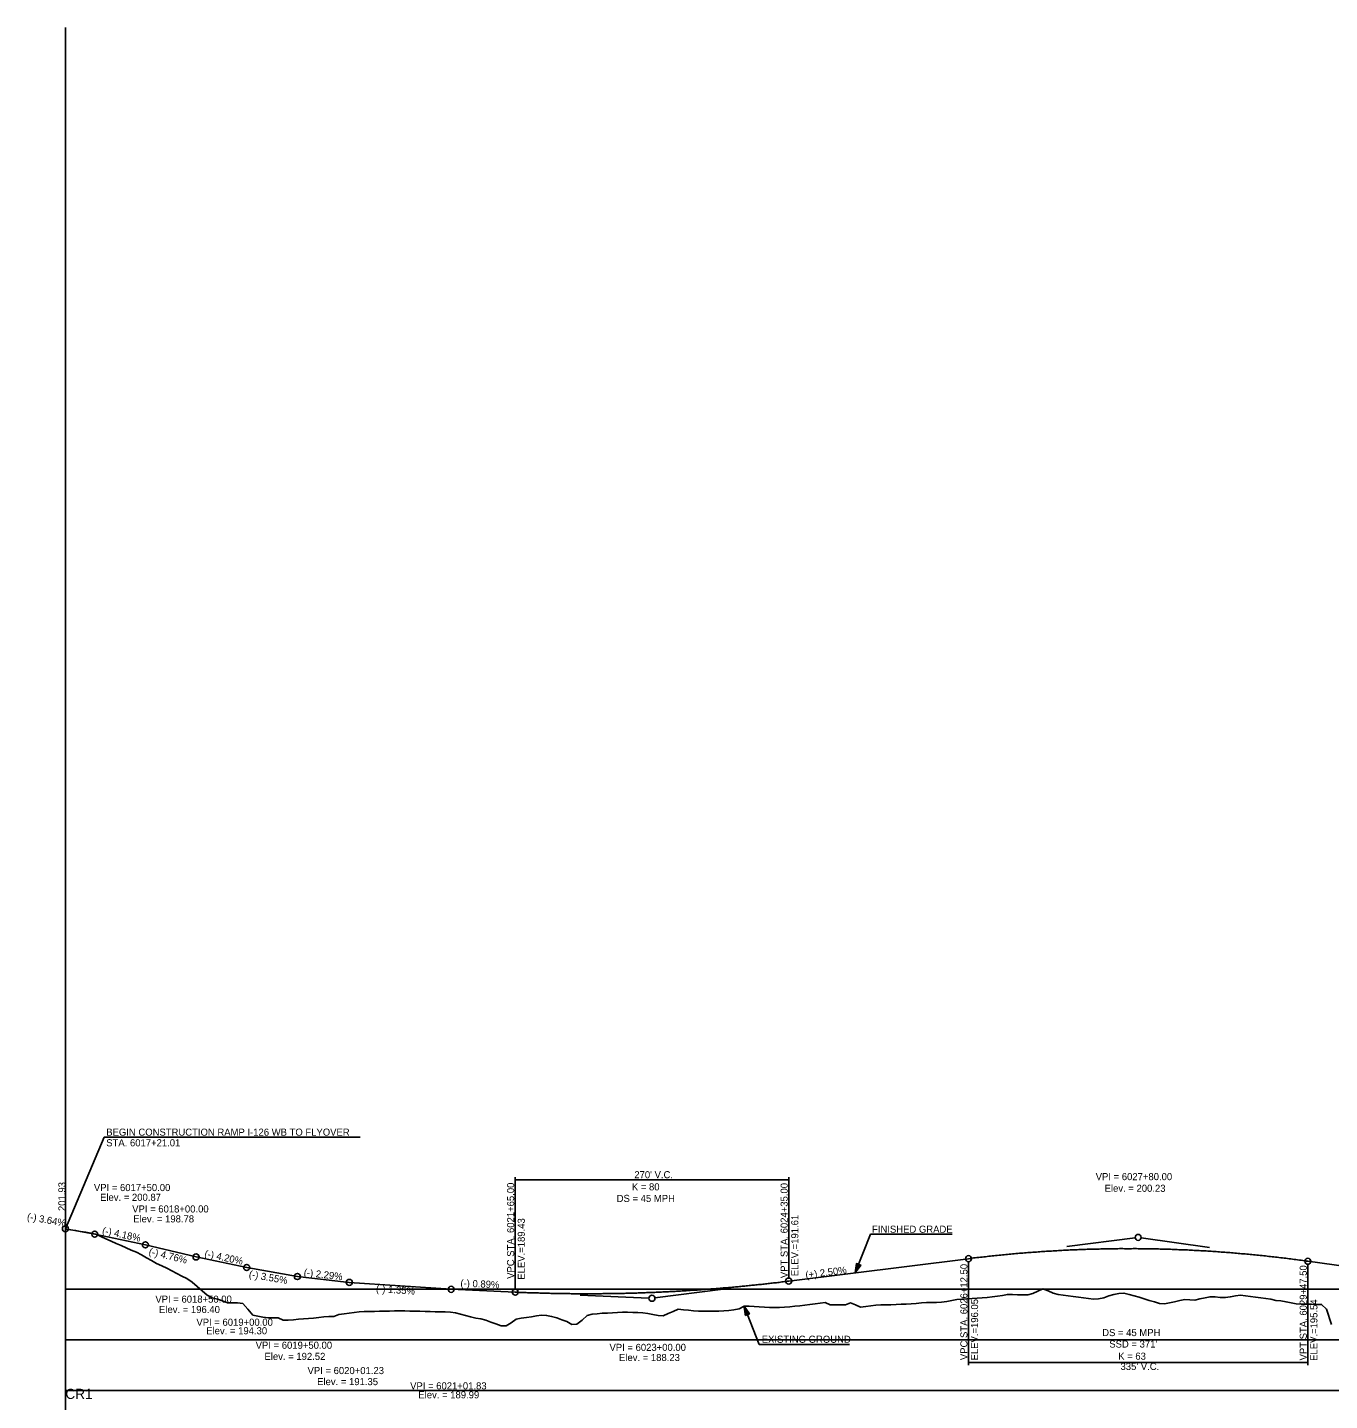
# Model space of a CAD drawing. Extents: x 69 to 2003113, y 512 to 837401.
# Drawn here: x 1923635 to 1924920, y 780753 to 782108 of the extents above; entities that cross this region are included whole.
import ezdxf

# ---------------------------------------------------------------- set-up
doc = ezdxf.new("R2010")
doc.units = 0
for name, color, linetype in [('BR_AUTO DIMENSION', 7, 'Continuous'), ('BR_BORDER LINES', 7, 'Continuous'), ('BR_CENTER LINE BASELINE', 7, 'Continuous'), ('BR_CONCRETE', 7, 'Continuous'), ('BR_GRID DOTS', 7, 'Continuous'), ('BR_GRID LINES', 7, 'Continuous'), ('BR_TEXT', 7, 'Continuous'), ('RD_PD_ALT1_TrvlWay', 7, 'Continuous'), ('RD_SHT_IplotShp', 7, 'Continuous')]:
    doc.layers.add(name, color=color, linetype=linetype)

msp = doc.modelspace()

# ---------------------------------------------------------------- linework, layer by layer
at = {"layer": 'BR_AUTO DIMENSION'}
for p, q in [((1923672.4, 779412.9), (1923672.4, 782108.2)), ((1923672.4, 780862.9), (1925947.9, 780862.9)), ((1923672.4, 780812.9), (1925947.9, 780812.9)), ((1923672.4, 780762.9), (1925947.9, 780762.9))]:
    msp.add_line(p, q, dxfattribs=at)
at = {"layer": 'BR_BORDER LINES'}
msp.add_line((1923672.4, 780662.9), (1923672.4, 781912.9), dxfattribs=at)
at = {"layer": 'BR_CENTER LINE BASELINE'}
for p, q in [((1924660.9, 780905.3), (1924728.4, 780913.7)), ((1924801.7, 780904.2), (1924734.3, 780913.7)), ((1924321.8, 780862.9), (1924254.3, 780854.4)), ((1924180.4, 780857.2), (1924248.4, 780854.2))]:
    msp.add_line(p, q, dxfattribs=at)
for centre in [(1923672.4, 780922.6), (1923701.4, 780917.3), (1924731.4, 780914.1), (1923751.4, 780906.8), (1923801.4, 780894.9), (1923851.4, 780884.4), (1923901.4, 780875.5), (1923952.6, 780869.7), (1924053.2, 780862.9), (1924251.4, 780854.1)]:
    msp.add_circle(centre, 3, dxfattribs=at)
at = {"layer": 'BR_GRID DOTS'}
for p, q in [((1924116.4, 780973.5), (1924116.4, 780863.1)), ((1924116.4, 780971), (1924386.4, 780971)), ((1924386.4, 780973.5), (1924386.4, 780874)), ((1924563.9, 780788.1), (1924563.9, 780890.1)), ((1924898.9, 780788.1), (1924898.9, 780887.6)), ((1924563.9, 780790.6), (1924898.9, 780790.6))]:
    msp.add_line(p, q, dxfattribs=at)
for points in [[(1923672.4, 780922.6), (1923710.7, 781012.9)], [(1923710.7, 781012.9), (1923963.5, 781012.9)]]:
    msp.add_lwpolyline(points, dxfattribs=at)
for centre in [(1924563.9, 780893.1), (1924898.9, 780890.6), (1924386.4, 780871), (1924116.4, 780860.1)]:
    msp.add_circle(centre, 3, dxfattribs=at)
at = {"layer": 'BR_GRID LINES'}
for p, q in [((1923672.4, 780922.6), (1923701.4, 780917.3)), ((1923701.4, 780917.3), (1923751.4, 780906.8)), ((1923751.4, 780906.8), (1923801.4, 780894.9)), ((1923801.4, 780894.9), (1923851.4, 780884.4)), ((1924386.4, 780871), (1924563.9, 780893.1)), ((1924898.9, 780890.6), (1925013.9, 780874.5)), ((1923851.4, 780884.4), (1923901.4, 780875.5)), ((1923901.4, 780875.5), (1923952.6, 780869.7)), ((1923952.6, 780869.7), (1924053.2, 780862.9)), ((1924053.2, 780862.9), (1924116.4, 780860.1))]:
    msp.add_line(p, q, dxfattribs=at)
for points in [[(1924563.9, 780893.1), (1924570.6, 780894), (1924577.3, 780894.7), (1924584, 780895.5), (1924590.7, 780896.2), (1924597.4, 780896.9), (1924604.1, 780897.5), (1924610.8, 780898.1), (1924617.5, 780898.7), (1924624.2, 780899.2), (1924630.9, 780899.7), (1924637.6, 780900.2), (1924644.3, 780900.6), (1924651, 780901), (1924657.7, 780901.4), (1924664.4, 780901.7), (1924671.1, 780902), (1924677.8, 780902.2), (1924684.5, 780902.5), (1924691.2, 780902.6), (1924697.9, 780902.8), (1924704.6, 780902.9), (1924711.3, 780903), (1924718, 780903), (1924724.7, 780903), (1924731.4, 780903), (1924738.1, 780902.9), (1924744.8, 780902.8), (1924751.5, 780902.7), (1924758.2, 780902.5), (1924764.9, 780902.3), (1924771.6, 780902), (1924778.3, 780901.8), (1924785, 780901.4), (1924791.7, 780901.1), (1924798.4, 780900.7), (1924805.1, 780900.3), (1924811.8, 780899.8), (1924818.5, 780899.3), (1924825.2, 780898.8), (1924831.9, 780898.2), (1924838.6, 780897.6), (1924845.3, 780897), (1924852, 780896.3), (1924858.7, 780895.6), (1924865.4, 780894.9), (1924872.1, 780894.1), (1924878.8, 780893.3), (1924885.5, 780892.4), (1924892.2, 780891.5), (1924898.9, 780890.6)], [(1924116.4, 780860.1), (1924121.8, 780859.8), (1924127.2, 780859.6), (1924132.6, 780859.4), (1924138, 780859.3), (1924143.4, 780859.1), (1924148.8, 780859), (1924154.2, 780858.8), (1924159.6, 780858.7), (1924165, 780858.7), (1924170.4, 780858.6), (1924175.8, 780858.5), (1924181.2, 780858.5), (1924186.6, 780858.5), (1924192, 780858.5), (1924197.4, 780858.5), (1924202.8, 780858.6), (1924208.2, 780858.6), (1924213.6, 780858.7), (1924219, 780858.8), (1924224.4, 780858.9), (1924229.8, 780859.1), (1924235.2, 780859.2), (1924240.6, 780859.4), (1924246, 780859.6), (1924251.4, 780859.8), (1924256.8, 780860), (1924262.2, 780860.3), (1924267.6, 780860.5), (1924273, 780860.8), (1924278.4, 780861.1), (1924283.8, 780861.4), (1924289.2, 780861.8), (1924294.6, 780862.1), (1924300, 780862.5), (1924305.4, 780862.9), (1924310.8, 780863.3), (1924316.2, 780863.7), (1924321.6, 780864.2), (1924327, 780864.6), (1924332.4, 780865.1), (1924337.8, 780865.6), (1924343.2, 780866.1), (1924348.6, 780866.7), (1924354, 780867.2), (1924359.4, 780867.8), (1924364.8, 780868.4), (1924370.2, 780869), (1924375.6, 780869.6), (1924381, 780870.3), (1924386.4, 780871)]]:
    msp.add_spline(points, degree=3, dxfattribs=at)
at = {"layer": 'BR_TEXT'}
for points in [[(1923672.4, 780922.2), (1923677.4, 780921.7), (1923682.4, 780921), (1923687.4, 780920.1), (1923692.4, 780919.2), (1923697.4, 780918.3), (1923702.4, 780917.3), (1923707.4, 780915), (1923712.4, 780912.7), (1923717.4, 780910.4), (1923722.4, 780908.2), (1923727.4, 780906.1), (1923732.4, 780903.8), (1923737.4, 780901.6), (1923742.4, 780899.4), (1923747.4, 780896.9), (1923752.4, 780894.1), (1923757.4, 780891.3), (1923762.4, 780888.5), (1923767.4, 780886.2), (1923772.4, 780883.9), (1923777.4, 780881.1), (1923782.4, 780878.4), (1923787.4, 780875.8), (1923792.4, 780873.7), (1923797.4, 780870.1), (1923802.4, 780865.7), (1923807.4, 780861.4), (1923812.4, 780857.1), (1923817.4, 780854.4), (1923822.4, 780853.2), (1923827.4, 780851.4), (1923832.4, 780849.6), (1923837.4, 780849.6), (1923842.4, 780849.6), (1923847.4, 780849), (1923852.4, 780843.2), (1923857.4, 780837.5), (1923862.4, 780836.3), (1923867.4, 780835.5), (1923872.4, 780834.8), (1923877.4, 780834.7), (1923882.4, 780834.7), (1923887.4, 780832.6), (1923892.4, 780832.5), (1923897.4, 780832.9), (1923902.4, 780833.3), (1923907.4, 780833.8), (1923912.4, 780834), (1923917.4, 780834.5), (1923922.4, 780835.2), (1923927.4, 780835.6), (1923932.4, 780835.9), (1923937.4, 780836.2), (1923942.4, 780838.1), (1923947.4, 780838.8), (1923952.4, 780839.5), (1923957.4, 780839.9), (1923962.4, 780840.8), (1923967.4, 780840.9), (1923972.4, 780841), (1923977.4, 780841.1), (1923982.4, 780841.2), (1923987.4, 780841.3), (1923992.4, 780841.4), (1923997.4, 780841.5), (1924002.4, 780841.6), (1924007.4, 780841.6), (1924012.4, 780841.4), (1924017.4, 780841.3), (1924022.4, 780841.2), (1924027.4, 780841.1), (1924032.4, 780840.9), (1924037.4, 780840.8), (1924042.4, 780840.7), (1924047.4, 780840.5), (1924052.4, 780840.3), (1924057.4, 780839.7), (1924062.4, 780838.3), (1924067.4, 780836.9), (1924072.4, 780835.6), (1924077.4, 780834.5), (1924082.4, 780833.7), (1924087.4, 780832.3), (1924092.4, 780830.6), (1924097.4, 780828.7), (1924102.4, 780826.8), (1924107.4, 780826.7), (1924112.4, 780829.9), (1924117.4, 780833.3), (1924122.4, 780834.3), (1924127.4, 780835), (1924132.4, 780835.6), (1924137.4, 780836.6), (1924142.4, 780837.3), (1924147.4, 780837.1), (1924152.4, 780836.1), (1924157.4, 780834.6), (1924162.4, 780832.8), (1924167.4, 780831.1), (1924172.4, 780828.3)], [(1924172.4, 780828.3), (1924177.4, 780828.5), (1924182.4, 780832.6), (1924187.4, 780837.1), (1924192.4, 780838.5), (1924197.4, 780838.8), (1924202.4, 780839.3), (1924207.4, 780839.4), (1924212.4, 780839.6), (1924217.4, 780839.9), (1924222.4, 780840.2), (1924227.4, 780840.2), (1924232.4, 780840.1), (1924237.4, 780839.9), (1924242.4, 780839.6), (1924247.4, 780839), (1924252.4, 780838.1), (1924257.4, 780837.2), (1924262.4, 780836.7), (1924267.4, 780838.9), (1924272.4, 780841.1), (1924277.4, 780843.4), (1924282.4, 780842.7), (1924287.4, 780842.2), (1924292.4, 780841.6), (1924297.4, 780841.3), (1924302.4, 780841.2), (1924307.4, 780841.3), (1924312.4, 780841.3), (1924317.4, 780841.2), (1924322.4, 780841.5), (1924327.4, 780841.9), (1924332.4, 780842.7), (1924337.4, 780843.5), (1924342.4, 780846.4), (1924347.4, 780846.2), (1924352.4, 780845.9), (1924357.4, 780845.6), (1924362.4, 780845.3), (1924367.4, 780845), (1924372.4, 780844.8), (1924377.4, 780845), (1924382.4, 780845.3), (1924387.4, 780845.6), (1924392.4, 780846.1), (1924397.4, 780846.7), (1924402.4, 780847.3), (1924407.4, 780847.9), (1924412.4, 780848.6), (1924417.4, 780849.2), (1924422.4, 780849.8), (1924427.4, 780847.6), (1924432.4, 780847.7), (1924437.4, 780847.6), (1924442.4, 780847.6), (1924447.4, 780849.5), (1924452.4, 780847.5), (1924457.4, 780845.4), (1924462.4, 780845.9), (1924467.4, 780846.7), (1924472.4, 780847.4), (1924477.4, 780847.7), (1924482.4, 780847.7), (1924487.4, 780847.7), (1924492.4, 780847.9), (1924497.4, 780848.1), (1924502.4, 780848.3), (1924507.4, 780848.4), (1924512.4, 780848.8), (1924517.4, 780849.5), (1924522.4, 780849.8), (1924527.4, 780849.8), (1924532.4, 780850), (1924537.4, 780850.2), (1924542.4, 780850.7), (1924547.4, 780851.7), (1924552.4, 780852.8), (1924557.4, 780853.3), (1924562.4, 780853.6), (1924567.4, 780853.9), (1924572.4, 780854.3), (1924577.4, 780854.6), (1924582.4, 780854.9), (1924587.4, 780855.5), (1924592.4, 780856.1), (1924597.4, 780856.7), (1924602.4, 780857.8), (1924607.4, 780857.8), (1924612.4, 780857.6), (1924617.4, 780857.5), (1924622.4, 780857.4), (1924627.4, 780858.8), (1924632.4, 780861), (1924637.4, 780863.2), (1924642.4, 780861.3), (1924647.4, 780859), (1924652.4, 780857.8), (1924657.4, 780857.1), (1924662.4, 780856.5), (1924667.4, 780855.8), (1924672.4, 780855.1)], [(1924672.4, 780855.1), (1924677.4, 780854.4), (1924682.4, 780853.7), (1924687.4, 780853.2), (1924692.4, 780853.6), (1924697.4, 780854.6), (1924702.4, 780856.3), (1924707.4, 780857.9), (1924712.4, 780858.9), (1924717.4, 780859.1), (1924722.4, 780857.8), (1924727.4, 780856.4), (1924732.4, 780855), (1924737.4, 780853.5), (1924742.4, 780852), (1924747.4, 780850.5), (1924752.4, 780849), (1924757.4, 780848.5), (1924762.4, 780849.6), (1924767.4, 780850.6), (1924772.4, 780851.7), (1924777.4, 780852.7), (1924782.4, 780852.6), (1924787.4, 780852.3), (1924792.4, 780853.4), (1924797.4, 780854.4), (1924802.4, 780855.5), (1924807.4, 780855.4), (1924812.4, 780854.9), (1924817.4, 780854.7), (1924822.4, 780855.6), (1924827.4, 780856.4), (1924832.4, 780857.1), (1924837.4, 780856.5), (1924842.4, 780855.9), (1924847.4, 780855.2), (1924852.4, 780854.6), (1924857.4, 780853.9), (1924862.4, 780853.1), (1924867.4, 780851.9), (1924872.4, 780851.5), (1924877.4, 780850.4), (1924882.4, 780849.7), (1924887.4, 780848.7), (1924892.4, 780848.1), (1924897.4, 780848.3), (1924902.4, 780848.2), (1924907.4, 780848), (1924912.4, 780847.9), (1924917.4, 780843.2), (1924922.4, 780828.3)]]:
    msp.add_lwpolyline(points, dxfattribs=at)
at = {"layer": 'RD_PD_ALT1_TrvlWay'}
for p, q in [((1924452.1, 780879.3), (1924467.1, 780917.2)), ((1924467.1, 780917.2), (1924547.9, 780917.2)), ((1924452.1, 780879.3), (1924453.3, 780888.5)), ((1924455.4, 780887.6), (1924452.1, 780879.3)), ((1924452.1, 780879.3), (1924457.5, 780886.8)), ((1924453.3, 780888.5), (1924457.5, 780886.8)), ((1924342.4, 780846.4), (1924357.3, 780808.4)), ((1924345.7, 780838), (1924342.4, 780846.4)), ((1924342.4, 780846.4), (1924347.8, 780838.8)), ((1924342.4, 780846.4), (1924343.6, 780837.2)), ((1924343.6, 780837.2), (1924347.8, 780838.8)), ((1924357.3, 780808.4), (1924446.5, 780808.4))]:
    msp.add_line(p, q, dxfattribs=at)
for points in [[(1924455.3, 780887.5), (1924452.3, 780879.8), (1924455.3, 780887.6), (1924452.3, 780880.1), (1924455.2, 780887.6), (1924452.4, 780880.4), (1924455.1, 780887.6), (1924452.4, 780880.7), (1924455, 780887.7), (1924452.5, 780881.2), (1924454.9, 780887.8), (1924452.5, 780881.8), (1924454.8, 780887.8), (1924452.6, 780882.2), (1924454.7, 780887.8), (1924452.7, 780882.6), (1924454.6, 780887.8), (1924452.7, 780883), (1924454.5, 780887.9), (1924452.8, 780883.4), (1924454.4, 780887.9), (1924452.8, 780883.9), (1924454.3, 780888), (1924452.9, 780884.5), (1924454.2, 780888), (1924452.9, 780884.9), (1924454.1, 780888.1), (1924453, 780885.5), (1924454, 780888.1), (1924453.1, 780886), (1924453.9, 780888.2), (1924453.2, 780886.4), (1924453.8, 780888.2), (1924453.2, 780886.8), (1924453.7, 780888.3), (1924453.3, 780887.3), (1924453.6, 780888.2), (1924453.4, 780887.9), (1924453.5, 780888.2)], [(1924452.4, 780879.8), (1924455.5, 780887.5), (1924452.6, 780880), (1924455.6, 780887.5), (1924452.7, 780880.3), (1924455.6, 780887.5), (1924452.9, 780880.5), (1924455.7, 780887.4), (1924453.1, 780880.7), (1924455.8, 780887.4), (1924453.3, 780881), (1924455.9, 780887.4), (1924453.5, 780881.3), (1924456, 780887.4), (1924453.7, 780881.6), (1924456.1, 780887.3), (1924454, 780882), (1924456.2, 780887.3), (1924454.2, 780882.3), (1924456.2, 780887.3), (1924454.4, 780882.6), (1924456.3, 780887.2), (1924454.7, 780882.9), (1924456.4, 780887.1), (1924455, 780883.4), (1924456.5, 780887.1), (1924455.2, 780883.7), (1924456.6, 780887.1), (1924455.5, 780884.1), (1924456.6, 780887.1), (1924455.7, 780884.5), (1924456.7, 780887), (1924456, 780884.8), (1924456.8, 780886.9), (1924456.2, 780885.1), (1924456.9, 780886.9), (1924456.5, 780885.5), (1924457, 780886.9), (1924456.7, 780885.8), (1924457.2, 780886.9), (1924456.9, 780886), (1924457.3, 780886.7), (1924457.4, 780886.8), (1924457.2, 780886.7)], [(1924345.6, 780838.1), (1924342.5, 780845.9), (1924345.5, 780838), (1924342.6, 780845.5), (1924345.4, 780838), (1924342.6, 780845.2), (1924345.3, 780838), (1924342.6, 780844.9), (1924345.2, 780837.9), (1924342.7, 780844.4), (1924345.1, 780837.8), (1924342.8, 780843.8), (1924345, 780837.8), (1924342.8, 780843.4), (1924344.9, 780837.8), (1924342.9, 780843), (1924344.8, 780837.8), (1924343, 780842.6), (1924344.8, 780837.7), (1924343, 780842.2), (1924344.6, 780837.7), (1924343.1, 780841.7), (1924344.5, 780837.6), (1924343.2, 780841.2), (1924344.4, 780837.6), (1924343.2, 780840.7), (1924344.3, 780837.5), (1924343.3, 780840.1), (1924344.2, 780837.5), (1924343.4, 780839.6), (1924344.1, 780837.4), (1924343.4, 780839.2), (1924344, 780837.4), (1924343.4, 780838.8), (1924343.9, 780837.3), (1924343.5, 780838.3), (1924343.8, 780837.4), (1924343.6, 780837.7), (1924343.7, 780837.4)], [(1924342.6, 780845.8), (1924345.7, 780838.1), (1924342.8, 780845.6), (1924345.8, 780838.1), (1924343, 780845.3), (1924345.9, 780838.1), (1924343.1, 780845.1), (1924345.9, 780838.2), (1924343.3, 780844.9), (1924346, 780838.2), (1924343.5, 780844.6), (1924346.1, 780838.2), (1924343.7, 780844.3), (1924346.2, 780838.2), (1924344, 780844), (1924346.3, 780838.3), (1924344.2, 780843.6), (1924346.4, 780838.3), (1924344.4, 780843.3), (1924346.5, 780838.4), (1924344.7, 780843), (1924346.6, 780838.4), (1924344.9, 780842.7), (1924346.6, 780838.5), (1924345.2, 780842.2), (1924346.7, 780838.5), (1924345.4, 780841.9), (1924346.8, 780838.5), (1924345.7, 780841.5), (1924346.9, 780838.5), (1924346, 780841.1), (1924347, 780838.6), (1924346.2, 780840.8), (1924347, 780838.7), (1924346.5, 780840.5), (1924347.1, 780838.7), (1924346.7, 780840.1), (1924347.3, 780838.7), (1924346.9, 780839.8), (1924347.4, 780838.7), (1924347.1, 780839.6), (1924347.5, 780838.9), (1924347.6, 780838.8), (1924347.5, 780838.9)]]:
    msp.add_lwpolyline(points, dxfattribs=at)

# ---------------------------------------------------------------- texts
at = {"layer": 'BR_BORDER LINES'}
msp.add_text('CR1', height=10, dxfattribs=at).set_placement((1923672.4, 780754.7))
at = {"layer": 'BR_CENTER LINE BASELINE'}
for s, rotation, p in [('(-) 3.64%', 349.6873, (1923634.1, 780931.5)), ('(-) 4.18%', 348.1878, (1923708.2, 780917.7)), ('(-) 4.76%', 346.6041, (1923754.2, 780897.1)), ('(-) 4.20%', 348.1337, (1923809.2, 780895)), ('(-) 3.55%', 349.924, (1923853.1, 780874.7)), ('(-) 2.29%', 353.4747, (1923907.4, 780876.2)), ('(-) 0.89%', 357.4563, (1924062.2, 780865.6)), ('(+) 2.50%', 7.125, (1924403.4, 780873.6)), ('(-) 1.35%', 356.1443, (1923978.8, 780860.2))]:
    msp.add_text(s, height=7, rotation=rotation, dxfattribs=at).set_placement(p)
at = {"layer": 'BR_CONCRETE'}
for s, p in [('VPC STA. 6021+65.00 ', (1924115.4, 780873.2)), ('VPT STA. 6024+35.00 ', (1924385.4, 780873.9)), ('ELEV.=189.43', (1924125.9, 780872.4)), ('ELEV.=191.61', (1924395.9, 780875.8)), ('VPC STA. 6026+12.50 ', (1924562.9, 780793)), ('VPT STA. 6029+47.50 ', (1924897.9, 780792.7)), ('ELEV.=196.05', (1924573.4, 780792.7)), ('ELEV.=195.54', (1924908.4, 780792.3))]:
    msp.add_text(s, height=7, rotation=90, dxfattribs=at).set_placement(p)
at = {"layer": 'BR_GRID DOTS'}
for s, p in [('K = 80', (1924231.6, 780960.5)), ("270' V.C.", (1924234, 780972.5)), ('DS = 45 MPH', (1924216.6, 780949.1)), ('DS = 45 MPH', (1924695.9, 780816.7)), ("SSD = 371'", (1924702.9, 780805.4)), ('K = 63', (1924711.7, 780793.4)), ("335' V.C.", (1924714, 780783.3))]:
    msp.add_text(s, height=7, dxfattribs=at).set_placement(p)
at = {"layer": 'RD_PD_ALT1_TrvlWay'}
for s, p in [('FINISHED GRADE', (1924468.7, 780918.7)), ('EXISTING GROUND', (1924359.8, 780810.1))]:
    msp.add_text(s, height=7, dxfattribs=at).set_placement(p)
at = {"layer": 'RD_SHT_IplotShp'}
for s, p in [('BEGIN CONSTRUCTION RAMP I-126 WB TO FLYOVER', (1923712.7, 781014.5)), ('STA. 6017+21.01', (1923712.7, 781004)), ('VPI = 6017+50.00', (1923700.5, 780959.8)), ('VPI = 6027+80.00', (1924689.5, 780970.6)), ('Elev. = 200.87', (1923706.6, 780950.2)), ('Elev. = 200.23', (1924698.3, 780959.1)), ('VPI = 6018+00.00', (1923738.3, 780938.7)), ('Elev. = 198.78', (1923739.3, 780928.9)), ('VPI = 6018+50.00', (1923761.2, 780849.7)), ('Elev. = 196.40', (1923764.8, 780839.5)), ('VPI = 6019+00.00', (1923801.7, 780826.9)), ('Elev. = 194.30', (1923811.4, 780818.5)), ('VPI = 6019+50.00', (1923860.2, 780804.2)), ('VPI = 6023+00.00', (1924209.5, 780802.1)), ('Elev. = 192.52', (1923868.9, 780793.2)), ('Elev. = 188.23', (1924218.9, 780792.1)), ('VPI = 6020+01.23', (1923911.4, 780779.2)), ('Elev. = 191.35', (1923920.9, 780768.3)), ('VPI = 6021+01.83', (1924012.7, 780764.1)), ('Elev. = 189.99', (1924020.8, 780755.3))]:
    msp.add_text(s, height=7, dxfattribs=at).set_placement(p)
msp.add_text('201.93', height=7, rotation=90, dxfattribs=at).set_placement((1923672.4, 780940.1))

doc.saveas('drawing.dxf')
